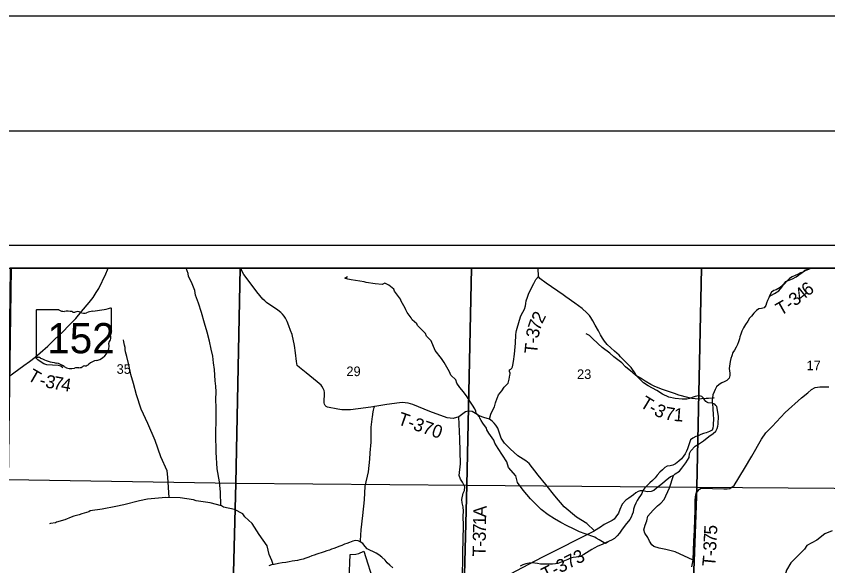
# Model space of a CAD drawing. Extents: x -19 to 40.8, y -1.8 to 26.1.
# Drawn here: x 4.462 to 8.007, y 19.6 to 22 of the extents above; entities that cross this region are included whole.
import ezdxf

# ---------------------------------------------------------------- set-up
doc = ezdxf.new("R2010")
doc.units = 0
for name, color, linetype in [('Default', 7, 'Continuous'), ('GM_X_Rail_Line', 7, 'Continuous'), ('GM_X_Section', 7, 'Continuous'), ('GM_X_Section_Text', 7, 'Continuous'), ('GM_X_State_Location', 7, 'Continuous'), ('GM_X_State_Route', 7, 'Continuous'), ('GM_X_Township_Road_Text', 7, 'Continuous'), ('GM_X_Unincorporated_Text', 7, 'Continuous'), ('RW_P_Text', 7, 'Continuous'), ('SH_Border', 7, 'Continuous'), ('SH_Cut_Line', 7, 'Continuous'), ('SH_Data', 7, 'Continuous')]:
    doc.layers.add(name, color=color, linetype=linetype)

msp = doc.modelspace()

# ---------------------------------------------------------------- linework, layer by layer
at = {"layer": 'Default'}
for points in [[(5.4394, 20.9), (4.44, 20.9), (4.4266, 19.9772), (5.4217, 19.9611)], [(6.4506, 20.9), (5.4394, 20.9), (5.4217, 19.9611), (6.4302, 19.9522)], [(7.4553, 20.9), (6.4506, 20.9), (6.4302, 19.9522), (7.4345, 19.9428)], [(8.4567, 20.9), (7.4553, 20.9), (7.4345, 19.9428), (8.4338, 19.9356)]]:
    msp.add_lwpolyline(points, close=True, dxfattribs=at)
at = {"layer": 'GM_X_Rail_Line'}
for points in [[(4.5441, 20.5118), (4.567, 20.5305), (4.5999, 20.5599), (4.6285, 20.5882), (4.6646, 20.6221), (4.6915, 20.6488), (4.7226, 20.6804), (4.7465, 20.7113), (4.7801, 20.7497), (4.7975, 20.7718), (4.811, 20.7931), (4.8219, 20.8113), (4.8536, 20.8758), (4.8597, 20.8924), (4.8635, 20.9)], [(4.4291, 20.4263), (4.4947, 20.4749), (4.5198, 20.4926), (4.5441, 20.5118)]]:
    msp.add_lwpolyline(points, dxfattribs=at)
at = {"layer": 'GM_X_Section'}
for points in [[(5.3548, 19.8636), (5.3536, 19.9216), (5.3498, 19.9672), (5.3401, 20.0241), (5.3351, 20.0964), (5.3334, 20.1744), (5.3349, 20.2422), (5.3356, 20.2913), (5.3342, 20.3267), (5.3344, 20.3594), (5.3332, 20.3841), (5.3313, 20.4081), (5.3297, 20.4324), (5.3274, 20.4575), (5.3239, 20.4864), (5.32, 20.516), (5.3138, 20.5463), (5.3064, 20.5808), (5.2963, 20.621), (5.2842, 20.66), (5.271, 20.7065), (5.2582, 20.7463), (5.2443, 20.7818), (5.2413, 20.8023), (5.2278, 20.8393), (5.2149, 20.8631), (5.2132, 20.8768), (5.2035, 20.9)], [(7.9336, 20.9), (7.9233, 20.8947), (7.9113, 20.889), (7.8982, 20.8829), (7.8881, 20.8788), (7.8742, 20.8722), (7.8637, 20.8677), (7.8513, 20.862), (7.8401, 20.8548), (7.8287, 20.8438), (7.8177, 20.832), (7.8081, 20.823), (7.7984, 20.8147), (7.782, 20.8058), (7.7714, 20.8024), (7.7606, 20.7949), (7.7542, 20.7825), (7.7488, 20.7709), (7.7439, 20.7586), (7.7393, 20.7466), (7.7362, 20.7366), (7.7286, 20.7261), (7.7168, 20.7235), (7.7059, 20.7216), (7.6958, 20.7148), (7.6844, 20.7034), (7.673, 20.6909), (7.6653, 20.6811), (7.6569, 20.6687), (7.6472, 20.6535), (7.6388, 20.6396), (7.6321, 20.6253), (7.6264, 20.6114), (7.6229, 20.6006), (7.6206, 20.5907), (7.6168, 20.5776), (7.613, 20.5664), (7.6072, 20.5545), (7.5989, 20.542), (7.5927, 20.5316), (7.5879, 20.5173), (7.5837, 20.505), (7.5806, 20.4927), (7.5791, 20.482), (7.5775, 20.4713), (7.5766, 20.4618), (7.5773, 20.4515), (7.5788, 20.4409), (7.5784, 20.4306), (7.5757, 20.4195), (7.5657, 20.4093), (7.5537, 20.4032), (7.544, 20.3987), (7.5317, 20.3915), (7.521, 20.3816), (7.5148, 20.37), (7.5098, 20.36), (7.5045, 20.3468), (7.5027, 20.3331), (7.5022, 20.3236), (7.5025, 20.3129), (7.5036, 20.3023), (7.5047, 20.2909), (7.5051, 20.2795), (7.5058, 20.2673), (7.5062, 20.2559), (7.5069, 20.2449), (7.5072, 20.2339), (7.5068, 20.2243), (7.506, 20.2129), (7.5052, 20.2018), (7.5013, 20.1922)], [(7.0472, 19.7054), (7.0354, 19.6968), (7.0297, 19.7005), (7.0087, 19.7135), (6.9953, 19.7208), (6.9896, 19.7257), (6.9474, 19.7391), (6.9222, 19.7489), (6.8963, 19.7618), (6.8689, 19.7751), (6.8414, 19.7891), (6.8135, 19.805), (6.7849, 19.8232), (6.7546, 19.8466), (6.7089, 19.8923), (6.6761, 19.9306), (6.6517, 19.9633), (6.6448, 19.9925), (6.612, 20.03), (6.6052, 20.0539), (6.5667, 20.1118), (6.5527, 20.136), (6.548, 20.1492), (6.5259, 20.1797), (6.5181, 20.1932), (6.5157, 20.2012), (6.5002, 20.2226), (6.4928, 20.2347), (6.487, 20.2453), (6.485, 20.2513), (6.4746, 20.2626), (6.4715, 20.2667), (6.4687, 20.275), (6.4644, 20.2856), (6.4554, 20.3018), (6.4438, 20.3188), (6.4309, 20.338), (6.4151, 20.3601), (6.3996, 20.3793), (6.3861, 20.397), (6.3817, 20.4121), (6.3598, 20.4323), (6.3546, 20.4467), (6.3312, 20.4878), (6.3188, 20.5054), (6.2922, 20.5396), (6.274, 20.5827), (6.254, 20.6029), (6.2497, 20.6139), (6.2247, 20.639), (6.2147, 20.6495), (6.2111, 20.6562), (6.1908, 20.6746), (6.1873, 20.6825), (6.1698, 20.7065), (6.1632, 20.7186), (6.1612, 20.7258), (6.1484, 20.7454), (6.1429, 20.7563), (6.1409, 20.7639), (6.1235, 20.7872), (6.1145, 20.8), (6.1114, 20.8079), (6.0899, 20.8251), (6.0808, 20.8299), (6.0777, 20.8321), (6.0724, 20.8343), (6.0607, 20.8291), (6.0297, 20.8321), (5.9907, 20.8371), (5.9812, 20.8408), (5.9251, 20.849), (5.9099, 20.8521), (5.897, 20.8565), (5.9086, 20.8632)], [(7.503, 20.3357), (7.511, 20.3333), (7.5038, 20.332), (7.4861, 20.3306), (7.4762, 20.3304), (7.4555, 20.3286), (7.4426, 20.3276), (7.4135, 20.3309), (7.396, 20.3348), (7.3569, 20.3452), (7.3367, 20.3529), (7.2984, 20.3652), (7.2801, 20.3721), (7.2478, 20.3841), (7.234, 20.3923), (7.2088, 20.4059), (7.1958, 20.4149), (7.1687, 20.4315), (7.1541, 20.4446), (7.1231, 20.4692), (7.1069, 20.4861), (7.0728, 20.5121), (7.0548, 20.5286), (7.0207, 20.5535), (7.0042, 20.5696), (6.9769, 20.5946), (6.9661, 20.6063), (6.952, 20.6133)], [(5.1299, 19.8978), (5.1245, 19.9871), (5.1206, 20.0148), (5.0935, 20.076), (5.0685, 20.1479), (5.0362, 20.2213), (5.0076, 20.2843), (4.9869, 20.3468), (4.9743, 20.3968), (4.9627, 20.4351), (4.9532, 20.4772), (4.9451, 20.5136), (4.9394, 20.5348), (4.9373, 20.5443), (4.9372, 20.553), (4.9344, 20.564), (4.9315, 20.578), (4.9298, 20.5871)], [(5.9644, 19.7055), (5.965, 19.7102), (5.968, 19.7574), (5.9752, 19.8204), (5.9828, 19.8882), (5.9859, 19.9477), (6.0003, 20.0104), (6.0062, 20.0656), (6.0072, 20.0935), (6.0121, 20.1407), (6.0128, 20.1682), (6.0121, 20.1868), (6.0129, 20.2058), (6.0178, 20.2516), (6.0199, 20.2589), (6.0202, 20.263), (6.0222, 20.2802), (6.0246, 20.2913), (6.0283, 20.2982)], [(7.5013, 20.1922), (7.4897, 20.1865), (7.4754, 20.1811), (7.4634, 20.1773), (7.4521, 20.1735), (7.4408, 20.1682), (7.4299, 20.1641), (7.4176, 20.1568), (7.4072, 20.15), (7.403, 20.1366), (7.3939, 20.1108), (7.3897, 20.1004), (7.3836, 20.0884), (7.3767, 20.0783), (7.3672, 20.0669), (7.3561, 20.0567), (7.342, 20.0456), (7.33, 20.0399), (7.3179, 20.0372), (7.3054, 20.0353), (7.2957, 20.0297), (7.2853, 20.0198), (7.2728, 20.0084), (7.2621, 19.9963), (7.2522, 19.9849), (7.2415, 19.9731), (7.2297, 19.9617), (7.2179, 19.9507), (7.2076, 19.9401), (7.1988, 19.9292), (7.1946, 19.9165), (7.1888, 19.9068), (7.1819, 19.8963), (7.1747, 19.8846), (7.1685, 19.8738), (7.1625, 19.861), (7.1587, 19.8468), (7.1564, 19.8349), (7.1522, 19.8234), (7.1476, 19.8122), (7.1419, 19.8021), (7.1213, 19.7771), (7.106, 19.7553), (7.0965, 19.7432), (7.087, 19.7304), (7.0748, 19.7197), (7.0617, 19.7124), (7.0516, 19.7076), (7.0389, 19.7014), (7.0212, 19.6937), (7.0025, 19.6851), (6.9868, 19.6773), (6.9763, 19.6709), (6.964, 19.6644), (6.9528, 19.6572), (6.9416, 19.6497), (6.9285, 19.6428), (6.9187, 19.6394), (6.9074, 19.6375), (6.8953, 19.636), (6.8836, 19.6334), (6.8712, 19.628), (6.8566, 19.6215), (6.8419, 19.6157), (6.828, 19.6103), (6.8174, 19.6081), (6.8049, 19.6069), (6.7916, 19.6073), (6.7813, 19.6069), (6.7711, 19.607), (6.7616, 19.6067), (6.7517, 19.6079), (6.7383, 19.6105), (6.7268, 19.6121), (6.7158, 19.6125), (6.7029, 19.6113), (6.6885, 19.6082), (6.6753, 19.6047), (6.6626, 19.5986)], [(5.584, 19.6054), (5.5786, 19.6234), (5.5665, 19.6487), (5.5586, 19.6867), (5.5226, 19.7371), (5.492, 19.7849), (5.4597, 19.8144), (5.4523, 19.8273), (5.4146, 19.8457), (5.3671, 19.8563), (5.3583, 19.8626), (5.3082, 19.8755), (5.2472, 19.8836), (5.2366, 19.8888), (5.1782, 19.8969), (5.112, 19.8981), (5.0999, 19.8976), (5.035, 19.8904), (5, 19.8833), (4.9315, 19.8662), (4.8972, 19.8588), (4.8369, 19.8467), (4.7853, 19.8394), (4.7789, 19.8362), (4.7481, 19.827), (4.736, 19.823), (4.7139, 19.8165), (4.7018, 19.8125), (4.6737, 19.8002), (4.6383, 19.7909), (4.6327, 19.7874), (4.6108, 19.7843), (4.6074, 19.7839)], [(8.026, 19.7527), (7.9933, 19.74), (7.9586, 19.712), (7.9148, 19.6892), (7.9056, 19.6723), (7.8454, 19.6135), (7.8263, 19.5812), (7.821, 19.5613), (7.7909, 19.5064), (7.7846, 19.4804), (7.7829, 19.4675), (7.7767, 19.4575)], [(6.1073, 19.5915), (6.0937, 19.6024), (6.0823, 19.6135), (6.0736, 19.6247), (6.0595, 19.6379), (6.0452, 19.6481), (6.0343, 19.6546), (6.0223, 19.6604), (6.0061, 19.6682), (5.9949, 19.6747), (5.9859, 19.6847), (5.976, 19.697), (5.9647, 19.7054), (5.9551, 19.7089), (5.9436, 19.7108), (5.9327, 19.707), (5.9177, 19.7016), (5.9064, 19.6978), (5.8962, 19.6945), (5.8842, 19.6891), (5.8707, 19.6842), (5.8602, 19.6796), (5.8496, 19.6759), (5.8395, 19.6721), (5.8297, 19.6684), (5.818, 19.665), (5.8071, 19.6612), (5.794, 19.6566), (5.7842, 19.654), (5.7744, 19.6507), (5.7638, 19.6469), (5.7533, 19.6435), (5.7398, 19.6378), (5.7274, 19.6332), (5.715, 19.6294), (5.7002, 19.6259), (5.6897, 19.6236), (5.6791, 19.6221), (5.667, 19.6202), (5.6545, 19.6176), (5.6394, 19.6152), (5.6238, 19.6124), (5.608, 19.6096), (5.5887, 19.6063), (5.5773, 19.6041), (5.5653, 19.5999)]]:
    msp.add_lwpolyline(points, dxfattribs=at)
at = {"layer": 'GM_X_State_Route'}
msp.add_line((6.7429, 20.8633), (6.742, 20.9), dxfattribs=at)
for points in [[(8.9, 15.8791), (8.9, 20.9), (4.4356, 20.9), (4.4289, 20.4268), (4.4141, 19.3749), (4.4038, 18.6476), (4.3932, 17.8891)], [(6.3955, 20.2501), (6.37, 20.2432), (6.3442, 20.2461), (6.2683, 20.2746), (6.1936, 20.3047), (6.1736, 20.31), (6.1604, 20.3124), (6.1512, 20.3127), (6.1354, 20.3122), (6.0805, 20.3042), (6.0103, 20.2933), (5.956, 20.285), (5.9215, 20.2807), (5.9039, 20.2808), (5.8838, 20.2817), (5.866, 20.2846), (5.8218, 20.2921), (5.8151, 20.2952), (5.8112, 20.3005), (5.8083, 20.3065), (5.8075, 20.312), (5.8082, 20.3568), (5.8064, 20.3656), (5.8023, 20.375), (5.7965, 20.3843), (5.7933, 20.3895), (5.7759, 20.4041), (5.728, 20.4433), (5.6986, 20.4662), (5.6896, 20.4752), (5.6857, 20.4925), (5.6819, 20.5297), (5.6767, 20.5626), (5.667, 20.6108), (5.6601, 20.6281), (5.6531, 20.6477), (5.6453, 20.6664), (5.6383, 20.6811), (5.6324, 20.6899), (5.6244, 20.6994), (5.617, 20.7062), (5.6052, 20.716), (5.5557, 20.7494), (5.5474, 20.7565), (5.5395, 20.7644), (5.5132, 20.7972), (5.484, 20.8357), (5.4565, 20.8728), (5.4494, 20.8857), (5.4432, 20.9)], [(7.8792, 20.8692), (7.8809, 20.8704), (7.8868, 20.8748), (7.8974, 20.8821), (7.9065, 20.8905), (7.9158, 20.8943), (7.9254, 20.8997), (7.9256, 20.9)], [(6.6314, 20.476), (6.6342, 20.4919), (6.6378, 20.5245), (6.6434, 20.5722), (6.6447, 20.6094), (6.6454, 20.6202), (6.6476, 20.6281), (6.6605, 20.6722), (6.6658, 20.6914), (6.675, 20.7075), (6.6825, 20.7201), (6.6868, 20.7348), (6.6874, 20.745), (6.6894, 20.7576), (6.6947, 20.7731), (6.7011, 20.791), (6.7222, 20.8322), (6.7314, 20.8501), (6.7429, 20.8633)], [(6.8627, 20.7752), (6.8506, 20.7838), (6.7765, 20.8343), (6.7487, 20.8548), (6.7429, 20.8633)], [(7.7508, 20.7768), (7.7741, 20.7888), (7.7936, 20.8011), (7.8061, 20.8168), (7.8153, 20.8306), (7.8239, 20.8416), (7.841, 20.8488), (7.8533, 20.8539), (7.8692, 20.8618), (7.8792, 20.8692)], [(7.419, 19.6246), (7.3405, 19.6611), (7.2994, 19.6717), (7.2698, 19.6769), (7.2464, 19.685), (7.2377, 19.6916), (7.2281, 19.7071), (7.2213, 19.7241), (7.2083, 19.7428), (7.203, 19.7573), (7.2092, 19.7781), (7.2162, 19.7969), (7.2206, 19.8174), (7.2438, 19.8424), (7.2629, 19.8619), (7.2772, 19.8739), (7.2922, 19.8901), (7.3152, 19.9402), (7.333, 19.9946), (7.3397, 20.001), (7.3596, 20.0133), (7.3696, 20.0267), (7.3874, 20.0503), (7.4008, 20.0729), (7.4027, 20.0901), (7.4086, 20.1025), (7.427, 20.1226), (7.4471, 20.1341), (7.4641, 20.1457), (7.4876, 20.1646), (7.5057, 20.1774), (7.5176, 20.188), (7.524, 20.1998), (7.5263, 20.2101), (7.5278, 20.219), (7.529, 20.2531), (7.5227, 20.2951), (7.5185, 20.3006), (7.5136, 20.3052), (7.5088, 20.3076), (7.5025, 20.3101), (7.4843, 20.3123), (7.4784, 20.3144), (7.4745, 20.3176), (7.4692, 20.3231), (7.4623, 20.3336), (7.4564, 20.3388), (7.4508, 20.3411), (7.4437, 20.3418), (7.4351, 20.341), (7.4272, 20.3396), (7.4181, 20.3365), (7.4021, 20.3302), (7.3909, 20.3282), (7.3707, 20.3282), (7.34, 20.3306), (7.3125, 20.3359), (7.2843, 20.3498), (7.2602, 20.3663), (7.2228, 20.3864), (7.2023, 20.399), (7.1711, 20.4298), (7.1668, 20.4384), (7.148, 20.4663), (7.1017, 20.5126), (7.095, 20.52), (7.0757, 20.5373), (7.0433, 20.5662), (7.0311, 20.5817), (7.0228, 20.5945), (7.0139, 20.6089), (7.005, 20.6255), (6.9908, 20.6515), (6.9805, 20.6699), (6.9717, 20.6838), (6.9656, 20.6938), (6.954, 20.7054), (6.9332, 20.7231), (6.9024, 20.747), (6.8627, 20.7752)], [(4.6656, 20.4643), (4.656, 20.4724), (4.6443, 20.4749), (4.5948, 20.4773), (4.5822, 20.4822), (4.5702, 20.4895), (4.5557, 20.5002), (4.5441, 20.5118)], [(6.5644, 20.3356), (6.5689, 20.3467), (6.5836, 20.3644), (6.5931, 20.3804), (6.6104, 20.3981), (6.6145, 20.4155), (6.6181, 20.4332), (6.6191, 20.438), (6.6188, 20.4418), (6.6171, 20.4493), (6.6161, 20.4553), (6.6228, 20.4588), (6.6269, 20.463), (6.6302, 20.4691), (6.6314, 20.476)], [(7.4133, 19.5955), (7.419, 19.6246), (7.4216, 19.707), (7.4252, 19.7558), (7.4265, 19.8038), (7.4271, 19.8416), (7.4277, 19.8853), (7.4291, 19.9015), (7.4316, 19.9152), (7.4379, 19.9249), (7.4464, 19.9344), (7.4544, 19.9384), (7.5528, 19.9367), (7.5677, 19.9364), (7.5786, 19.9381), (7.5977, 19.9508), (7.6432, 20.0244), (7.6748, 20.079), (7.7174, 20.153), (7.7355, 20.1805), (7.7632, 20.2087), (7.82, 20.2698), (7.8927, 20.3331), (7.9192, 20.3555), (7.9363, 20.3697), (7.9516, 20.3783), (7.9723, 20.3815), (8.0117, 20.3821)], [(6.5293, 20.2402), (6.5352, 20.2619), (6.542, 20.2786), (6.5515, 20.2942), (6.556, 20.3119), (6.5627, 20.3316), (6.5644, 20.3356)], [(6.9875, 19.7531), (6.9536, 19.785), (6.9085, 19.8129), (6.856, 19.8573), (6.8147, 19.9061), (6.7748, 19.9558), (6.7422, 19.9965), (6.7021, 20.0475), (6.6881, 20.0583), (6.6526, 20.0804), (6.6187, 20.1108), (6.595, 20.1349), (6.5808, 20.1579), (6.5659, 20.2008), (6.5565, 20.2149), (6.5495, 20.2235), (6.5404, 20.2323), (6.5293, 20.2402), (6.5045, 20.2475), (6.4844, 20.255), (6.4676, 20.2652), (6.4529, 20.2736), (6.4361, 20.2756), (6.4245, 20.2719), (6.3955, 20.2501)], [(6.412, 19.6359), (6.4123, 19.6561), (6.415, 19.7752), (6.4147, 19.8174), (6.416, 19.8384), (6.4144, 19.8577), (6.4095, 19.875), (6.4081, 19.889), (6.4148, 19.9174), (6.4192, 19.929), (6.4215, 19.9455), (6.4121, 19.9628), (6.4108, 19.9652), (6.4019, 19.9784), (6.3967, 19.9949), (6.4027, 20.0449), (6.4001, 20.154), (6.3955, 20.2501)], [(7.333, 19.9946), (7.3198, 19.9888), (7.2964, 19.9699), (7.285, 19.96), (7.259, 19.9386), (7.2474, 19.9293), (7.2353, 19.9245), (7.2174, 19.9238), (7.2002, 19.927), (7.1875, 19.927), (7.179, 19.9247), (7.1689, 19.9194), (7.1575, 19.9094), (7.1381, 19.8959), (7.1241, 19.8862), (7.1089, 19.8688), (7.0986, 19.8456), (7.092, 19.8302), (7.0811, 19.8144), (7.0738, 19.8042), (7.0651, 19.7972), (7.0504, 19.7906), (7.0294, 19.7805), (7.0136, 19.7683), (6.9875, 19.7531)], [(6.7287, 19.622), (6.7652, 19.6413), (6.9875, 19.7531)], [(5.9023, 19.2192), (5.921, 19.6494), (5.9448, 19.6506), (5.9583, 19.6543), (5.9805, 19.6643), (6.0254, 19.5216)], [(6.3805, 19.4372), (6.3897, 19.4462), (6.4085, 19.4527), (6.7287, 19.622)], [(6.4096, 19.4709), (6.4097, 19.4727), (6.412, 19.6359)]]:
    msp.add_lwpolyline(points, dxfattribs=at)
at = {"layer": 'GM_X_Unincorporated_Text'}
for p, q in [((4.5485, 20.7141), (4.5485, 20.514)), ((4.6483, 20.7176), (4.5518, 20.7176)), ((4.8781, 20.6178), (4.8781, 20.7225)), ((4.8781, 20.6179), (4.8781, 20.6178))]:
    msp.add_line(p, q, dxfattribs=at)
for centre, major_axis, start_param, end_param in [((4.5523, 20.7146), (0.00382, 0), 1.712693, 3.28349), ((4.6713, 20.7408), (0.037, 0), 4.042523, 4.731795), ((4.6836, 20.6052), (0.133, 0), 1.404758, 1.657858), ((4.7138, 20.7156), (0.0107, 0), 3.836095, 5.185415), ((4.7294, 20.6925), (0.0222, 0), 0.950623, 2.079405), ((4.7581, 20.7242), (0.0267, 0), 4.081561, 5.145723), ((4.8053, 20.6564), (0.0703, 0), 1.699011, 2.107814), ((4.7607, 20.9904), (0.3495, 0), 4.814394, 5.042369), ((4.8745, 20.723), (0.00367, 0), 6.141152, 7.989035), ((4.8773, 20.6102), (0.00568, 0), 1.883978, 3.671073), ((4.8412, 20.5969), (0.0341, 0), 5.934695, 6.695948), ((4.8742, 20.6174), (0.00393, 0), 5.05454, 6.418171), ((4.7803, 20.5607), (0.0874, 0), 5.101752, 6.440018), ((4.8913, 20.574), (0.0248, 0), 2.387724, 3.262537), ((4.5524, 20.5136), (0.00385, 0), 3.00124, 4.508301), ((4.5529, 20.534), (0.0294, 0), 4.665946, 4.897461), ((4.559, 20.5025), (0.0106, 0), 0.519207, 1.627899), ((4.6928, 20.6823), (0.2524, 0), 4.195997, 4.488961), ((4.8172, 20.4578), (0.0479, 0), 1.647645, 2.488434), ((4.6175, 20.4241), (0.079, 0), 0.823519, 1.323587), ((4.7029, 20.5015), (0.0501, 0), 4.026481, 4.996735), ((4.7319, 20.4323), (0.0412, 0), 1.495662, 1.94098), ((4.7356, 20.4865), (0.0267, 0), 4.691044, 5.507374), ((4.7597, 20.4671), (0.00752, 0), 1.147584, 2.315152), ((4.7565, 20.4946), (0.0282, 0), 4.937069, 5.64225)]:
    msp.add_ellipse(centre, major_axis=major_axis, ratio=0.8, start_param=start_param, end_param=end_param, dxfattribs=at)
at = {"layer": 'RW_P_Text'}
for points in [[(4.4266, 19.9772), (5.4217, 19.9611), (5.3949, 18.9546), (4.411, 18.9653), (4.4251, 19.8945)], [(5.4217, 19.9611), (6.4302, 19.9522), (6.4041, 18.9461), (5.3949, 18.9546)], [(6.4302, 19.9522), (7.4345, 19.9428), (7.3987, 18.9308), (6.4041, 18.9461)], [(7.4345, 19.9428), (8.4338, 19.9356), (8.4001, 18.9137), (7.3987, 18.9308)]]:
    msp.add_lwpolyline(points, close=True, dxfattribs=at)
at = {"layer": 'SH_Border'}
msp.add_lwpolyline([(1.5, 21.5), (33.5, 21.5), (33.5, 0.5), (1.5, 0.5)], close=True, dxfattribs=at)
at = {"layer": 'SH_Cut_Line'}
msp.add_lwpolyline([(0, 0), (34, 0), (34, 22), (0, 22)], close=True, dxfattribs=at)
at = {"layer": 'SH_Data'}
for p, q in [((2, 21), (9, 21)), ((2.1, 20.9), (8.9, 20.9))]:
    msp.add_line(p, q, dxfattribs=at)

# ---------------------------------------------------------------- texts
at = {"layer": 'GM_X_Section_Text'}
for s, p in [('17', (7.914, 20.4544)), ('35', (4.9003, 20.4384)), ('29', (5.904, 20.4284)), ('23', (6.9115, 20.4159))]:
    msp.add_text(s, height=0.04186, rotation=0, dxfattribs=at).set_placement(p)
at = {"layer": 'GM_X_State_Location'}
for s in ['s', 'r']:
    msp.add_text(s, height=0.000189, dxfattribs=at).set_placement((4.7096, 20.6008))
msp.add_text('152', height=0.000189, rotation=0, dxfattribs=at).set_placement((4.6428, 20.587))
at = {"layer": 'GM_X_Township_Road_Text'}
for s, height, rotation, p in [('4', 0.0568, 38.6208, (7.8913, 20.7528)), ('6', 0.0568, 37.3788, (7.9184, 20.7745)), ('3', 0.0568, 38.6367, (7.864, 20.731)), ('T', 0.0568, 29.418, (7.7998, 20.6908)), ('-', 0.0568, 35.8589, (7.8427, 20.7155)), ('2', 0.0568, 62.8624, (6.7591, 20.6545)), ('7', 0.0568, 71.4976, (6.7489, 20.6234)), ('3', 0.0568, 78.6115, (6.7424, 20.5909)), ('T', 0.0568, 84.3295, (6.7375, 20.5237)), ('-', 0.0568, 88.1323, (6.742, 20.5701)), ('T', 0.0568, 329.7206, (4.5073, 20.4143)), ('3', 0.0568, 349.1525, (4.5859, 20.3797)), ('7', 0.0568, 349.5521, (4.6204, 20.3731)), ('-', 0.0568, 345.1375, (4.5593, 20.3866)), ('4', 0.0568, 349.5502, (4.6545, 20.3668)), ('T', 0.0568, 328.8782, (7.1825, 20.2965)), ('-', 0.0568, 330.0266, (7.2199, 20.2739)), ('3', 0.0568, 333.8375, (7.2438, 20.2603)), ('7', 0.0568, 350.1359, (7.2919, 20.2395)), ('1', 0.0568, 355.5926, (7.3322, 20.2327)), ('T-370', 0.05682, 340.7819, (6.1242, 20.2192)), ('A', 0.0568, 88.007, (6.5146, 19.8114)), ('1', 0.0568, 88.7978, (6.5138, 19.7766)), ('3', 0.0568, 89.0164, (6.5126, 19.7067)), ('7', 0.0568, 88.9591, (6.5132, 19.7417)), ('5', 0.0568, 87.2987, (7.5227, 19.7351)), ('7', 0.0568, 86.5373, (7.5205, 19.6994)), ('T', 0.0568, 89.0228, (6.5115, 19.6409)), ('-', 0.0568, 89.0326, (6.5122, 19.6834)), ('3', 0.0568, 87.9752, (7.5193, 19.6648)), ('T-373', 0.05682, 26.9405, (6.7743, 19.5347)), ('T', 0.0568, 84.3295, (7.5142, 19.5948)), ('-', 0.0568, 88.4418, (7.5187, 19.6416))]:
    msp.add_text(s, height=height, rotation=rotation, dxfattribs=at).set_placement(p)
at = {"layer": 'GM_X_Unincorporated_Text'}
msp.add_text('152', height=0.13184, dxfattribs=at).set_placement((4.5975, 20.5281))

doc.saveas('drawing.dxf')
